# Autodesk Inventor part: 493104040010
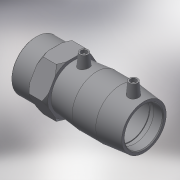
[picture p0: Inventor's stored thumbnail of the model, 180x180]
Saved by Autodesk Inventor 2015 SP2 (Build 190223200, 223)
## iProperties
Created: 2017-06
Part Number: 493104040010
Material: Generic
Description: PLASSON FEMALE TRANSITION COUPLER 40-1"
Document SubType Name: Modeling
Designer: KIM
Mass: 183.344 g
Surface Area: 410.108 cm^2
Volume: 183.344 cm^3
Density: 1 g/cm^3
Appearance: Default
Author: KIM
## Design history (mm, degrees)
derived "493104.ipt"
feature "Solid1::493104.ipt"
tag "TaggingFeature1"
body "Solid1"
other parameters: "d0" = 97, "d2" = 56, "d3" = 47, "d4" = 32.33333, "d5" = 50.4, "d6" = 38, "d8" = 168 deg, "d10" = 18.8, "d11" = 6.26667, "d29" = 46, "d30" = 14, "d31" = 33.95, "d34" = 5 deg, "d41" = 4, "d42" = 14, "d43" = 0, "d48" = 3, "d49" = 0, "d55" = 25, "d57" = 29, "d59" = 30.291, "d60" = 22.5, "d70" = 56, "d71" = 12.5, "d72" = 0, "d73" = 45 deg, "d74" = 2.9, "d75" = 45 deg, "d77" = 0.6, "d80" = 0.8, "L_" = 122, "L_1" = 47, "D_1" = 56, "A_" = 46, "d_2" = 12, "L_2" = 25, "D_" = 29, "R_p" = 30.291
